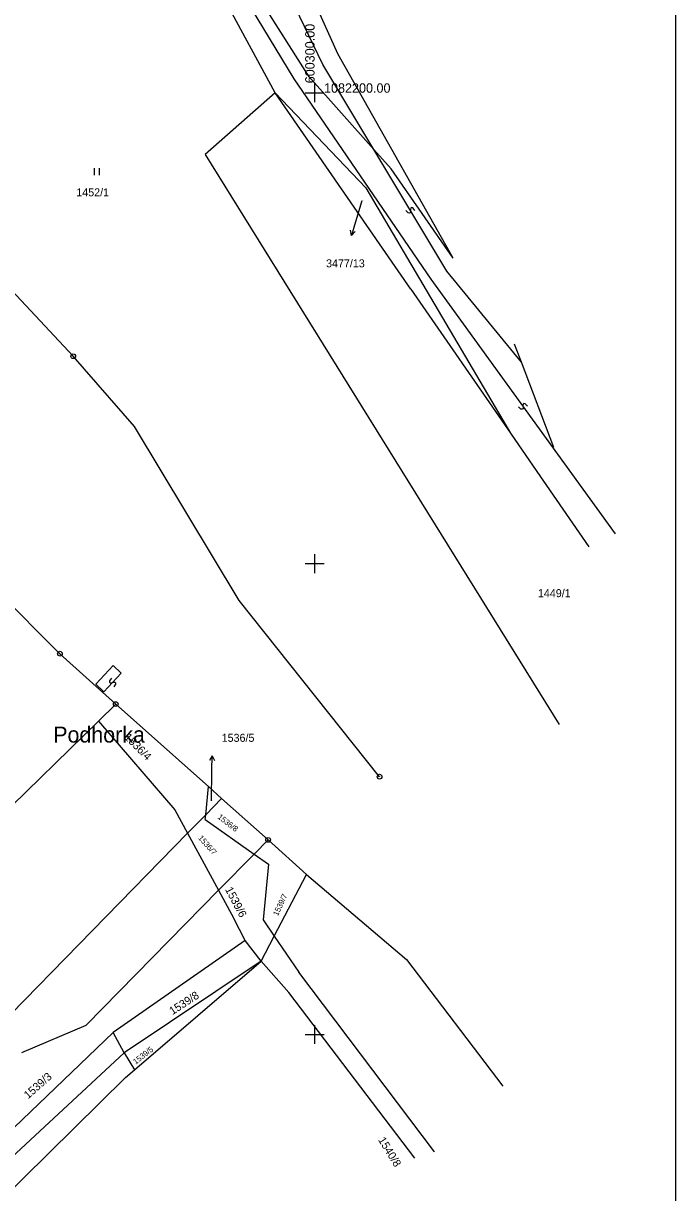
# Model space of a CAD drawing. Extents: x -601196 to -600262, y -1082523 to -1081922.
# Drawn here: x -600330.9 to -600261.6, y -1082316.8 to -1082192.6 of the extents above; entities that cross this region are included whole.
import ezdxf

# ---------------------------------------------------------------- set-up
doc = ezdxf.new("R2010")
doc.units = 0
for name, color, linetype in [('Vrstva 47', 7, 'Continuous'), ('Vrstva 59', 7, 'Continuous'), ('Vrstva 61', 7, 'Continuous'), ('Vrstva 63', 7, 'Continuous')]:
    doc.layers.add(name, color=color, linetype=linetype)

msp = doc.modelspace()

# ---------------------------------------------------------------- linework, layer by layer
at = {"layer": 'Vrstva 47'}
for p, q in [((-600297.54, -1082195.88), (-600313.35, -1082160.63)), ((-600299.12, -1082196.99), (-600308.42, -1082177.75)), ((-600304.18, -1082200.01), (-600315.09, -1082179.9)), ((-600312.05, -1082182.34), (-600302.2, -1082198.51)), ((-600300.57, -1082198.32), (-600310.6, -1082182.5)), ((-600285.29, -1082217.56), (-600297.54, -1082195.88)), ((-600293.69, -1082206.04), (-600299.12, -1082196.99)), ((-600302.2, -1082198.51), (-600287.64, -1082219.79)), ((-600300.57, -1082198.32), (-600293.69, -1082206.04)), ((-600304.18, -1082200.01), (-600311.64, -1082206.57)), ((-600289.79, -1082220.85), (-600304.18, -1082200.01)), ((-600294.54, -1082210.08), (-600304.18, -1082200.01)), ((-600311.64, -1082206.57), (-600274, -1082267.08)), ((-600285.94, -1082218.95), (-600293.69, -1082206.04)), ((-600293.69, -1082206.04), (-600291.88, -1082208.07)), ((-600325.65, -1082227.98), (-600344.89, -1082207.45)), ((-600323.38, -1082208.76), (-600323.38, -1082208.01)), ((-600322.88, -1082208.01), (-600322.88, -1082208.76)), ((-600285.29, -1082217.56), (-600291.88, -1082208.07)), ((-600294.54, -1082210.08), (-600279.2, -1082236.16)), ((-600294.98, -1082211.48), (-600295.65, -1082213.72)), ((-600290.06, -1082212.76), (-600290.29, -1082212.49)), ((-600289.93, -1082212.79), (-600290.06, -1082212.76)), ((-600289.84, -1082212.74), (-600289.93, -1082212.79)), ((-600289.81, -1082212.61), (-600289.84, -1082212.74)), ((-600289.79, -1082212.25), (-600289.82, -1082212.38)), ((-600289.82, -1082212.38), (-600289.81, -1082212.61)), ((-600289.7, -1082212.19), (-600289.79, -1082212.25)), ((-600289.57, -1082212.23), (-600289.7, -1082212.19)), ((-600289.34, -1082212.5), (-600289.57, -1082212.23)), ((-600295.65, -1082213.72), (-600296.09, -1082215.15)), ((-600296.09, -1082215.15), (-600296.18, -1082214.6)), ((-600296.09, -1082215.15), (-600295.7, -1082214.75)), ((-600278.03, -1082228.62), (-600285.94, -1082218.95)), ((-600287.64, -1082219.79), (-600268.06, -1082246.82)), ((-600289.79, -1082220.85), (-600279.2, -1082236.16)), ((-600278.03, -1082228.62), (-600278.77, -1082226.7)), ((-600319.12, -1082235.43), (-600325.65, -1082227.98)), ((-600274.57, -1082237.67), (-600278.03, -1082228.62)), ((-600278.07, -1082233.59), (-600278.32, -1082233.34)), ((-600277.94, -1082233.61), (-600278.07, -1082233.59)), ((-600277.85, -1082233.55), (-600277.94, -1082233.61)), ((-600277.84, -1082233.05), (-600277.87, -1082233.19)), ((-600277.87, -1082233.19), (-600277.83, -1082233.42)), ((-600277.83, -1082233.42), (-600277.85, -1082233.55)), ((-600277.76, -1082233), (-600277.84, -1082233.05)), ((-600277.62, -1082233.02), (-600277.76, -1082233)), ((-600277.38, -1082233.27), (-600277.62, -1082233.02)), ((-600308, -1082253.91), (-600319.12, -1082235.43)), ((-600279.2, -1082236.16), (-600276.39, -1082240.21)), ((-600276.39, -1082240.21), (-600270.86, -1082248.2)), ((-600335.96, -1082250.66), (-600327.06, -1082259.56)), ((-600293.1, -1082272.62), (-600308, -1082253.91)), ((-600327.06, -1082259.56), (-600321.13, -1082264.91)), ((-600321.4, -1082260.82), (-600323.24, -1082262.81)), ((-600320.54, -1082261.62), (-600321.4, -1082260.82)), ((-600322.38, -1082263.61), (-600320.54, -1082261.62)), ((-600321.58, -1082262.16), (-600321.78, -1082262.45)), ((-600321.78, -1082262.45), (-600321.78, -1082262.59)), ((-600323.24, -1082262.81), (-600322.38, -1082263.61)), ((-600321.78, -1082262.59), (-600321.7, -1082262.66)), ((-600321.7, -1082262.66), (-600321.56, -1082262.65)), ((-600321.56, -1082262.65), (-600321.35, -1082262.57)), ((-600321.35, -1082262.57), (-600321.21, -1082262.57)), ((-600321.14, -1082262.78), (-600321.34, -1082263.07)), ((-600321.21, -1082262.57), (-600321.14, -1082262.64)), ((-600321.14, -1082262.64), (-600321.14, -1082262.78)), ((-600321.13, -1082264.91), (-600322.97, -1082266.71)), ((-600321.13, -1082264.91), (-600311.28, -1082273.68)), ((-600337.62, -1082281.02), (-600322.97, -1082266.71)), ((-600322.97, -1082266.71), (-600314.85, -1082276.14)), ((-600310.89, -1082270.42), (-600311.15, -1082270.92)), ((-600310.92, -1082271.92), (-600310.89, -1082270.42)), ((-600310.89, -1082270.42), (-600310.65, -1082270.92)), ((-600310.97, -1082275.17), (-600310.92, -1082271.92)), ((-600311.57, -1082276.66), (-600311.28, -1082273.68)), ((-600311.28, -1082273.68), (-600309.88, -1082274.93)), ((-600311.57, -1082276.66), (-600309.88, -1082274.93)), ((-600309.88, -1082274.93), (-600304.94, -1082279.33)), ((-600314.85, -1082276.14), (-600313.5, -1082278.63)), ((-600313.5, -1082278.63), (-600311.57, -1082276.66)), ((-600311.62, -1082277.18), (-600311.57, -1082276.66)), ((-600311.62, -1082277.18), (-600306.43, -1082280.85)), ((-600420.14, -1082387.57), (-600313.5, -1082278.63)), ((-600313.5, -1082278.63), (-600310.2, -1082284.68)), ((-600306.43, -1082280.85), (-600304.94, -1082279.33)), ((-600304.94, -1082279.33), (-600300.85, -1082283.02)), ((-600306.43, -1082280.85), (-600310.2, -1082284.68)), ((-600306.43, -1082280.85), (-600304.91, -1082281.92)), ((-600304.91, -1082281.92), (-600305.46, -1082287.83)), ((-600304.28, -1082289.54), (-600300.85, -1082283.02)), ((-600300.85, -1082283.02), (-600290.25, -1082292.03)), ((-600324.28, -1082298.99), (-600310.2, -1082284.68)), ((-600310.2, -1082284.68), (-600308.57, -1082287.68)), ((-600307.36, -1082290.01), (-600308.57, -1082287.68)), ((-600305.46, -1082287.83), (-600304.28, -1082289.54)), ((-600305.68, -1082292.2), (-600304.28, -1082289.54)), ((-600304.28, -1082289.54), (-600301.66, -1082293.37)), ((-600307.36, -1082290.01), (-600321.42, -1082299.79)), ((-600305.68, -1082292.2), (-600307.36, -1082290.01)), ((-600305.68, -1082292.2), (-600320.22, -1082301.95)), ((-600319.15, -1082303.76), (-600305.68, -1082292.2)), ((-600305.68, -1082292.2), (-600302.74, -1082295.54)), ((-600290.25, -1082292.03), (-600280, -1082305.49)), ((-600287.25, -1082312.46), (-600301.66, -1082293.37)), ((-600289.34, -1082313.13), (-600302.74, -1082295.54)), ((-600331.1, -1082301.92), (-600324.28, -1082298.99)), ((-600321.42, -1082299.79), (-600375.67, -1082351.77)), ((-600320.22, -1082301.95), (-600321.42, -1082299.79)), ((-600320.22, -1082301.95), (-600346.46, -1082326.22)), ((-600320.22, -1082301.95), (-600319.15, -1082303.76)), ((-600344.96, -1082329.06), (-600320.08, -1082304.56)), ((-600320.08, -1082304.56), (-600319.15, -1082303.76))]:
    msp.add_line(p, q, dxfattribs=at)
for centre, radius in [((-600325.65, -1082227.98), 0.25), ((-600325.65, -1082227.98), 0.005), ((-600327.06, -1082259.56), 0.25), ((-600327.06, -1082259.56), 0.005), ((-600321.13, -1082264.91), 0.25), ((-600321.13, -1082264.91), 0.005), ((-600293.1, -1082272.62), 0.25), ((-600293.1, -1082272.62), 0.005), ((-600304.94, -1082279.33), 0.25), ((-600304.94, -1082279.33), 0.005)]:
    msp.add_circle(centre, radius, dxfattribs=at)
at = {"layer": 'Vrstva 59'}
msp.add_lwpolyline([(-600681.64, -1082515.69), (-600681.64, -1081921.69), (-600261.64, -1081921.69), (-600261.64, -1082515.69)], close=True, dxfattribs=at)
at = {"layer": 'Vrstva 61'}
for p, q in [((-600300, -1082199), (-600300, -1082201)), ((-600300, -1082199), (-600300, -1082201)), ((-600301, -1082200), (-600299, -1082200)), ((-600301, -1082200), (-600299, -1082200)), ((-600301, -1082250), (-600299, -1082250)), ((-600301, -1082250), (-600299, -1082250)), ((-600300, -1082249), (-600300, -1082251)), ((-600300, -1082249), (-600300, -1082251)), ((-600300, -1082299), (-600300, -1082301)), ((-600300, -1082299), (-600300, -1082301)), ((-600301, -1082300), (-600299, -1082300)), ((-600301, -1082300), (-600299, -1082300))]:
    msp.add_line(p, q, dxfattribs=at)

# ---------------------------------------------------------------- texts
at = {"layer": 'Vrstva 47'}
for s, height, p in [('1452/1', 0.85, (-600325.32, -1082211)), ('3477/13', 0.05, (-600294.98, -1082211.48)), ('3477/13', 0.85, (-600298.78, -1082218.54)), ('1449/1', 0.85, (-600276.27, -1082253.56)), ('Podhorka', 1.7, (-600327.77, -1082269)), ('1536/5', 0.85, (-600309.87, -1082268.92)), ('1536/5', 0.05, (-600310.97, -1082275.17))]:
    msp.add_text(s, height=height, dxfattribs=at).set_placement(p)
for s, height, rotation, p in [('1536/4', 0.85, 315, (-600320.29, -1082268.51)), ('1536/8', 0.6, 322.2, (-600310.36, -1082277.01)), ('1536/7', 0.6, 311.4, (-600312.41, -1082279.16)), ('1539/6', 0.85, 297.9, (-600309.54, -1082284.59)), ('1539/7', 0.6, 64.8, (-600303.91, -1082287.46)), ('1539/8', 0.85, 32.9584, (-600315.1, -1082297.95)), ('1539/5', 0.6, 37.8, (-600319.01, -1082303.2)), ('1539/3', 0.85, 41.4, (-600330.44, -1082306.89)), ('1540/8', 0.85, 301.5, (-600293.28, -1082311.19))]:
    msp.add_text(s, height=height, rotation=rotation, dxfattribs=at).set_placement(p)
at = {"layer": 'Vrstva 63'}
msp.add_text('600300.00', height=1, rotation=90, dxfattribs=at).set_placement((-600300, -1082199))
msp.add_text('1082200.00', height=1, dxfattribs=at).set_placement((-600299, -1082200))

doc.saveas('drawing.dxf')
